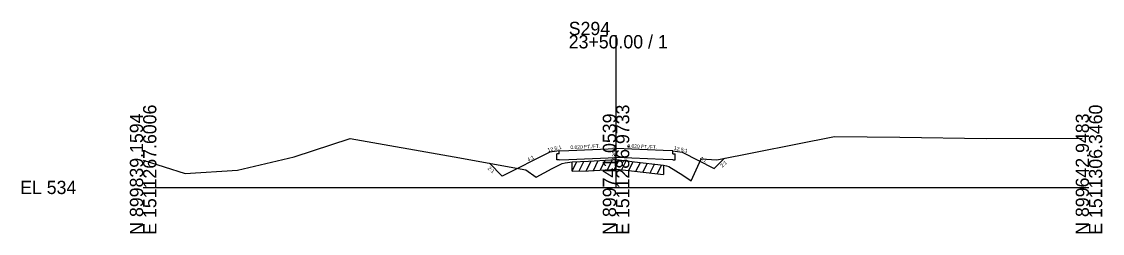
# Model space of a CAD drawing. Extents: x 974 to 2203, y -10 to 19041.
# Drawn here: x 1974.3 to 2202.8, y 6990.3 to 7035 of the extents above; entities that cross this region are included whole.
import ezdxf

# ---------------------------------------------------------------- set-up
doc = ezdxf.new("R2010")
doc.units = 0
for name, color, linetype in [('RD_GPK_XS_Cell', 7, 'Continuous'), ('RD_XS_Base', 7, 'Continuous'), ('RD_XS_EarthShd', 7, 'Continuous'), ('RD_XS_ExGround', 7, 'Continuous'), ('RD_XS_ExPaveRet', 7, 'Continuous'), ('RD_XS_Pave', 7, 'Continuous'), ('RD_XS_TX_Elev_EX', 7, 'Continuous'), ('RD_XS_TX_Slope', 7, 'Continuous')]:
    doc.layers.add(name, color=color, linetype=linetype)

msp = doc.modelspace()

# ---------------------------------------------------------------- linework, layer by layer
at = {"layer": 'RD_GPK_XS_Cell'}
for p, q in [((2100, 7000), (2100, 7032.15)), ((2000, 7000), (2100, 7000)), ((2100, 7000), (2200, 7000))]:
    msp.add_line(p, q, dxfattribs=at)
at = {"layer": 'RD_XS_Base'}
for p, q in [((2088, 7007.1), (2087.48, 7007.08)), ((2087.48, 7005.81), (2087.48, 7007.08)), ((2088, 7007.1), (2088, 7007.74)), ((2112, 7007.1), (2112, 7007.74)), ((2112, 7007.1), (2112.52, 7007.08)), ((2112.52, 7005.81), (2112.52, 7007.08)), ((2087.98, 7005.83), (2087.48, 7005.81)), ((2087.98, 7005.83), (2090, 7005.91)), ((2090, 7005.91), (2100, 7006.31)), ((2110, 7005.91), (2100, 7006.31)), ((2112.02, 7005.83), (2110, 7005.91)), ((2112.02, 7005.83), (2112.52, 7005.81))]:
    msp.add_line(p, q, dxfattribs=at)
at = {"layer": 'RD_XS_EarthShd'}
for p, q in [((2086, 7007.41), (2075.95, 7002.39)), ((2088, 7007.74), (2086, 7007.41)), ((2112, 7007.74), (2114, 7007.41)), ((2114, 7007.41), (2120.78, 7004.02)), ((2075.95, 7002.39), (2073.22, 7005.11)), ((2120.78, 7004.02), (2122.92, 7006.15))]:
    msp.add_line(p, q, dxfattribs=at)
at = {"layer": 'RD_XS_ExGround'}
msp.add_lwpolyline([(2000, 7005.72), (2008.91, 7002.96), (2019.96, 7003.63), (2031.92, 7006.46), (2043.8, 7010.3), (2065.77, 7006.46), (2080.92, 7003.72), (2083.12, 7002.16), (2086.47, 7004.02), (2088.59, 7005.03), (2089.25, 7005.17), (2090.7, 7005.42), (2094.15, 7005.53), (2100.09, 7005.89), (2103.92, 7005.43), (2110.06, 7004.73), (2110.66, 7004.54), (2111.13, 7004.41), (2114.09, 7002.57), (2115.87, 7001.39), (2118, 7006.05), (2121.34, 7005.84), (2146.18, 7010.72), (2159.98, 7010.6), (2178.25, 7010.3), (2198.57, 7010.43)], dxfattribs=at)
at = {"layer": 'RD_XS_ExPaveRet'}
for p, q in [((2090.7, 7003.42), (2091.72, 7005.46)), ((2090.7, 7003.42), (2090.7, 7005.42)), ((2092.2, 7003.47), (2093.22, 7005.5)), ((2093.7, 7003.52), (2094.73, 7005.57)), ((2095.2, 7003.6), (2096.23, 7005.66)), ((2096.7, 7003.69), (2097.73, 7005.75)), ((2098.2, 7003.78), (2099.23, 7005.84)), ((2099.7, 7003.87), (2100.68, 7005.82)), ((2101.2, 7003.76), (2102.15, 7005.64)), ((2102.7, 7003.58), (2103.65, 7005.46)), ((2104.2, 7003.4), (2105.15, 7005.29)), ((2105.7, 7003.23), (2106.65, 7005.12)), ((2107.2, 7003.05), (2108.15, 7004.94)), ((2108.7, 7002.88), (2109.65, 7004.77)), ((2110.06, 7004.73), (2110.06, 7002.73)), ((2090.7, 7003.42), (2094.15, 7003.53)), ((2094.15, 7003.53), (2100.09, 7003.89)), ((2100.09, 7003.89), (2103.92, 7003.43)), ((2103.92, 7003.43), (2110.06, 7002.73))]:
    msp.add_line(p, q, dxfattribs=at)
at = {"layer": 'RD_XS_Pave'}
for p, q in [((2088, 7007.74), (2090, 7007.82)), ((2090, 7007.82), (2100, 7008.22)), ((2110, 7007.82), (2100, 7008.22)), ((2112, 7007.74), (2110, 7007.82))]:
    msp.add_line(p, q, dxfattribs=at)

# ---------------------------------------------------------------- texts
at = {"layer": 'RD_GPK_XS_Cell'}
for s, p in [('S294', (2090, 7032.15)), ('23+50.00 / 1', (2090, 7029.35)), ('EL 534', (1974, 6998.6))]:
    msp.add_text(s, height=2.8, dxfattribs=at).set_placement(p)
for s, p in [('E 1511267.6006', (2002.8, 6990)), ('E 1511286.9733', (2102.8, 6990)), ('E 1511306.3460', (2202.8, 6990)), ('N 899839.1594', (2000, 6990)), ('N 899741.0539', (2100, 6990)), ('N 899642.9483', (2200, 6990))]:
    msp.add_text(s, height=2.8, rotation=90, dxfattribs=at).set_placement(p)
at = {"layer": 'RD_XS_TX_Elev_EX'}
msp.add_text('536.94', height=0.75, rotation=90, dxfattribs=at).set_placement((2100, 7005.89))
at = {"layer": 'RD_XS_TX_Slope'}
for s, height, rotation, p in [('0.020 FT./FT.', 0.7518, 357.604, (2102.4, 7008.38)), ('12.5:1', 0.778, 12.7511, (2085.61, 7007.49)), ('0.020 FT./FT.', 0.7518, 2.396, (2090.38, 7008.08)), ('12.5:1', 0.778, 347.2489, (2112.17, 7007.99)), ('4:1', 0.778, 26.3688, (2081.44, 7005.44)), ('4:1', 0.778, 333.6312, (2117.62, 7005.91)), ('2:1', 0.778, 40.6589, (2122.43, 7004.14)), ('2:1', 0.778, 319.3411, (2072.79, 7003.91))]:
    msp.add_text(s, height=height, rotation=rotation, dxfattribs=at).set_placement(p)

doc.saveas('drawing.dxf')
